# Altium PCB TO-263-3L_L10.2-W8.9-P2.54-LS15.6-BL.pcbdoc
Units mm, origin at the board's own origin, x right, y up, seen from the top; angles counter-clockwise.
Board outline 23.3 x 30.9 mm, 2 copper layers (Top Layer, Bottom Layer), stack 0 mm thick; 1 components, 0 nets, 4 pads, 0 vias.
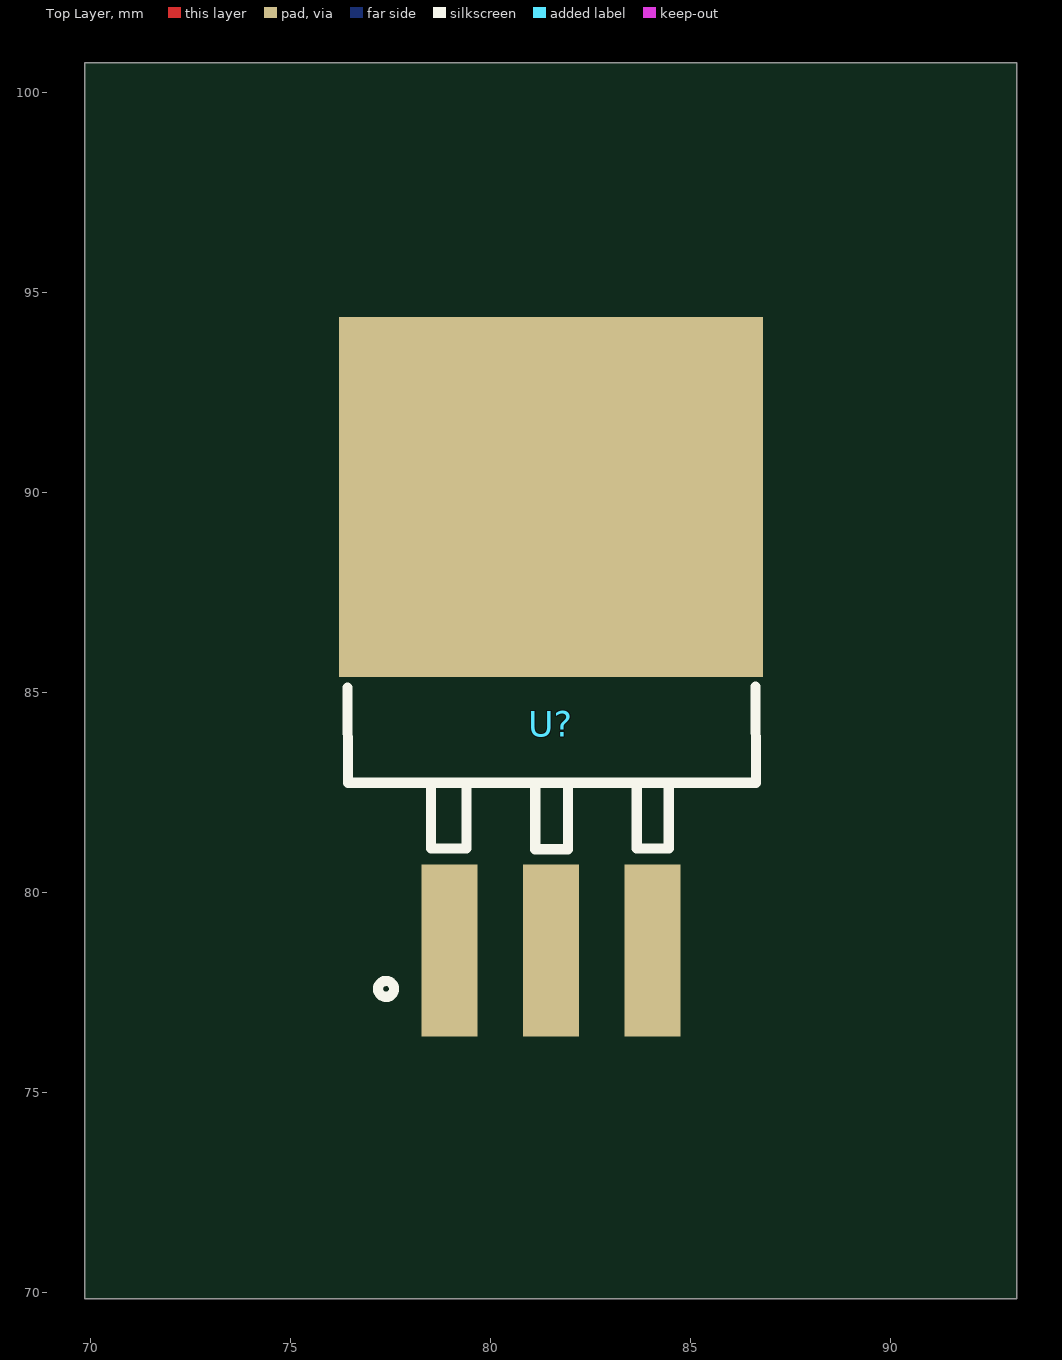
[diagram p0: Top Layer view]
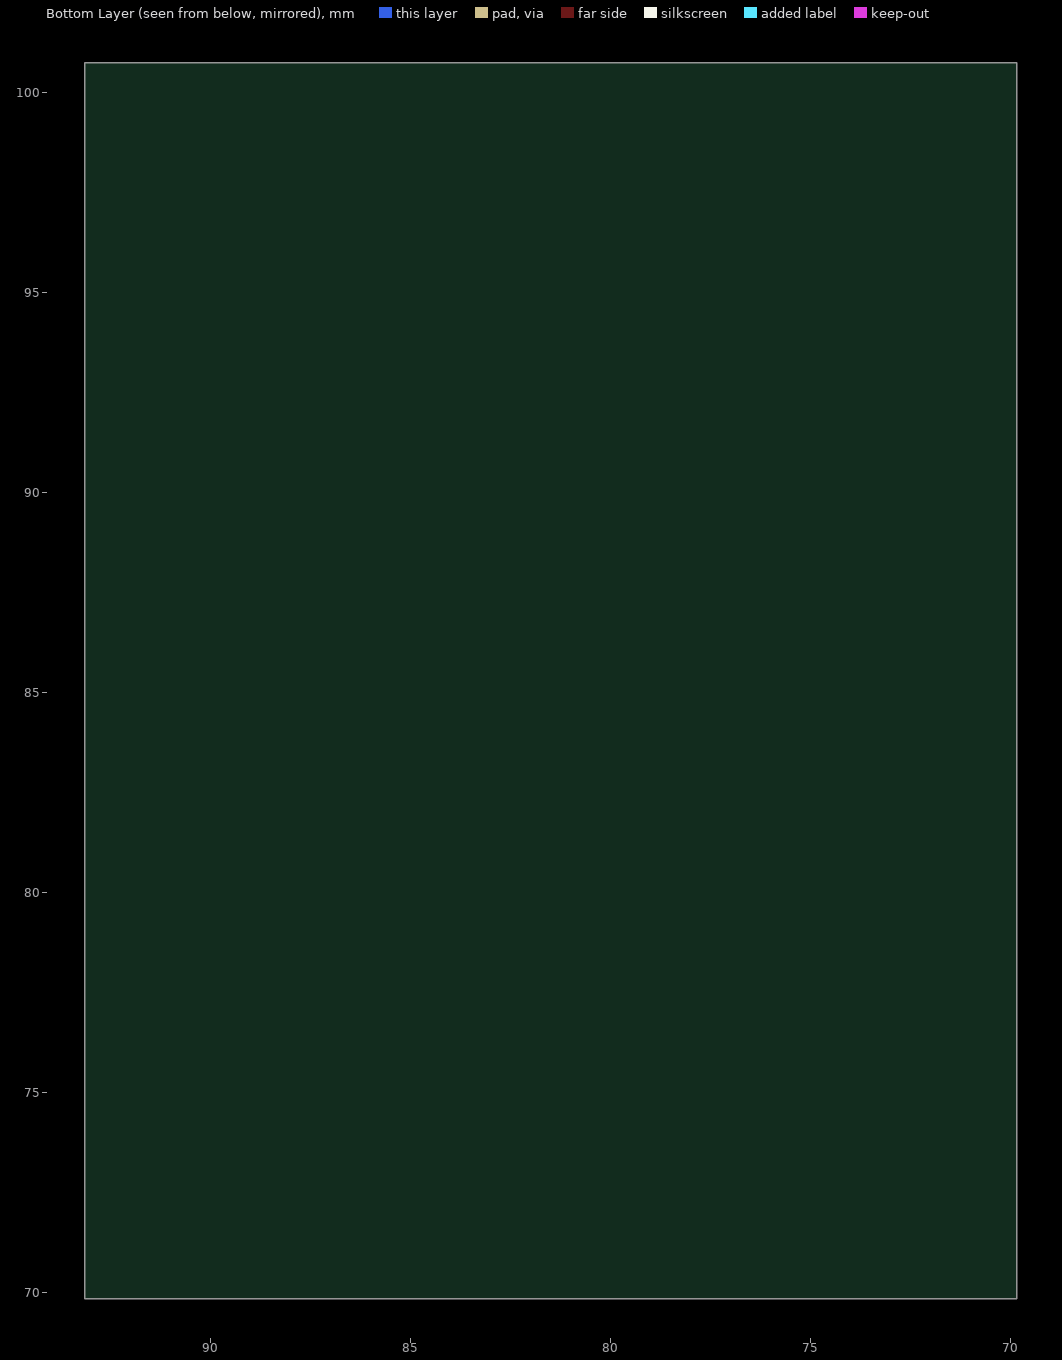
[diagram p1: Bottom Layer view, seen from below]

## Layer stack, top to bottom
Top Layer: signal copper (thickness not stored)
Bottom Layer: signal copper (thickness not stored)

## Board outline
93.15,69.85 69.85,69.85 69.85,100.75 93.15,100.75

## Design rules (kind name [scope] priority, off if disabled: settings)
PasteMaskExpansion "Paste Mask Expansion" [All] p1: expansion=0
SolderMaskExpansion "Solder Mask Expansion" [IsVia] p1: expansion=-25.4 istentingtop=TRUE
SolderMaskExpansion "Solder Mask Expansion" [All] p2: expansion=0.051 istentingtop=FALSE

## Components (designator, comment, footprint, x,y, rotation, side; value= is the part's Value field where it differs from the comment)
U? "" TO-263-3L_L10.2-W8.9-P2.54-LS15.6-BL 81.5,84.231 r0 top

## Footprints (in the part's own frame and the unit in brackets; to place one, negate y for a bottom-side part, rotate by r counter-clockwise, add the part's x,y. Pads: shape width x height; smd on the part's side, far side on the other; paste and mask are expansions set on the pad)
TO-263-3L_L10.2-W8.9-P2.54-LS15.6-BL [mm]
  rect 1.4x4.3 smd: 1(-2.54,-5.669) 2(0,-5.669) 3(2.54,-5.669)
  rect 10.6x9 smd paste+0 mask+0.05: 4(0,5.669)
  silkscreen extent -5.08,-6.83 5.13,0.92

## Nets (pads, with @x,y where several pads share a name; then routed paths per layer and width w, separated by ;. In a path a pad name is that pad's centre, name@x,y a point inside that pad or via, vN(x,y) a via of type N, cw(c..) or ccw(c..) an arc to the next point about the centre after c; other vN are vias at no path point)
pads on no net: U?.1 U?.2 U?.3 U?.4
